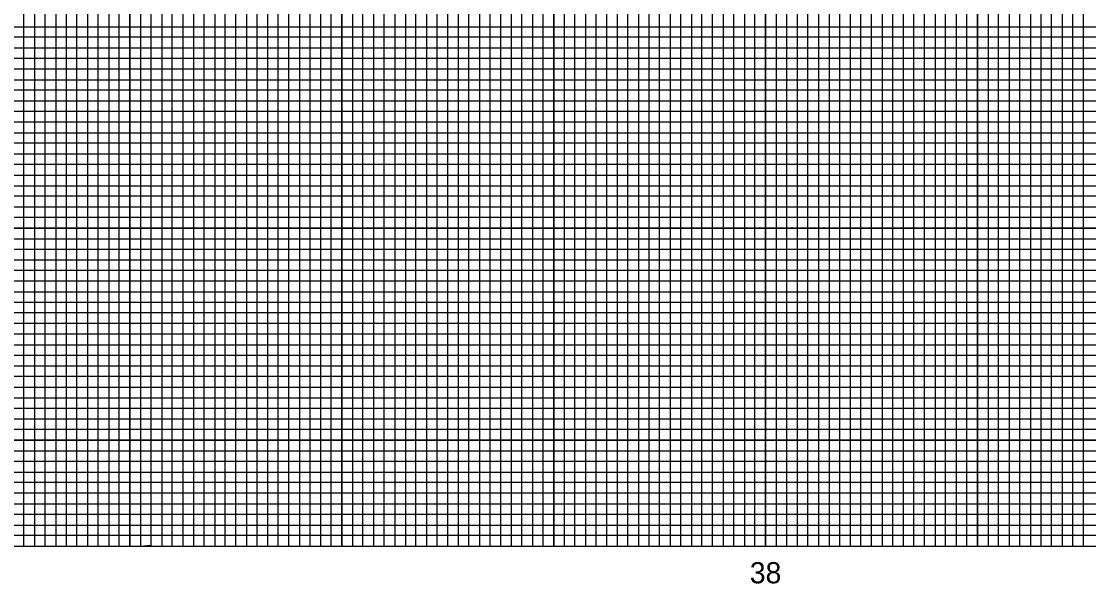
# Model space of a CAD drawing. Extents: x 1648862 to 1650739, y 844691 to 845791.
# Drawn here: x 1649828 to 1650332, y 845248 to 845514 of the extents above; entities that cross this region are included whole.
import ezdxf

# ---------------------------------------------------------------- set-up
doc = ezdxf.new("R2010")
doc.units = 0
for name, color, linetype in [('Prop Conc Barrier Precast Reinforced Single Face', 7, 'Continuous'), ('Prop Conc Expressway Gutter', 7, 'Continuous'), ('Prop DGN Element Guardrail', 7, 'Continuous'), ('Prop Dimension', 7, 'Continuous'), ('Prop Dimension Text', 7, 'Continuous'), ('Prop Easement Construction Station Offsets', 7, 'Continuous')]:
    doc.layers.add(name, color=color, linetype=linetype)

msp = doc.modelspace()

# ---------------------------------------------------------------- linework, layer by layer
at = {"layer": 'Prop Conc Expressway Gutter'}
for p, q in [((1649079.28, 845511.02), (1650479.28, 845511.02)), ((1650479.28, 845506.02), (1649079.28, 845506.02)), ((1649079.28, 845501.02), (1650479.28, 845501.02)), ((1650479.28, 845496.02), (1649079.28, 845496.02)), ((1649079.28, 845486.02), (1650479.28, 845486.02)), ((1650479.28, 845481.02), (1649079.28, 845481.02)), ((1649079.28, 845476.02), (1650479.28, 845476.02)), ((1650479.28, 845471.02), (1649079.28, 845471.02)), ((1649079.28, 845461.02), (1650479.28, 845461.02)), ((1650479.28, 845456.02), (1649079.28, 845456.02)), ((1649079.28, 845451.02), (1650479.28, 845451.02)), ((1650479.28, 845446.02), (1649079.28, 845446.02)), ((1649079.28, 845436.02), (1650479.28, 845436.02)), ((1650479.28, 845431.02), (1649079.28, 845431.02)), ((1649079.28, 845426.02), (1650479.28, 845426.02)), ((1650479.28, 845421.02), (1649079.28, 845421.02)), ((1649079.28, 845411.02), (1650479.28, 845411.02)), ((1650479.28, 845406.02), (1649079.28, 845406.02)), ((1649079.28, 845401.02), (1650479.28, 845401.02)), ((1650479.28, 845396.02), (1649079.28, 845396.02)), ((1649079.28, 845386.02), (1650479.28, 845386.02)), ((1650479.28, 845381.02), (1649079.28, 845381.02)), ((1650479.28, 845376.02), (1649079.28, 845376.02)), ((1650479.28, 845371.02), (1649079.28, 845371.02)), ((1649079.28, 845361.02), (1650479.28, 845361.02)), ((1650479.28, 845356.02), (1649079.28, 845356.02)), ((1649079.28, 845351.02), (1650479.28, 845351.02)), ((1650479.28, 845346.02), (1649079.28, 845346.02)), ((1649079.28, 845336.02), (1650479.28, 845336.02)), ((1650479.28, 845331.02), (1649079.28, 845331.02)), ((1649079.28, 845326.02), (1650479.28, 845326.02)), ((1650479.28, 845321.02), (1649079.28, 845321.02)), ((1649079.28, 845311.02), (1650479.28, 845311.02)), ((1650479.28, 845306.02), (1649079.28, 845306.02)), ((1649079.28, 845301.02), (1650479.28, 845301.02)), ((1650479.28, 845296.02), (1649079.28, 845296.02)), ((1649079.28, 845286.02), (1650479.28, 845286.02)), ((1650479.28, 845281.02), (1649079.28, 845281.02)), ((1649079.28, 845276.02), (1650479.28, 845276.02)), ((1650159.28, 845266.02), (1650164.28, 845266.02))]:
    msp.add_line(p, q, dxfattribs=at)
for points in [[(1649834.28, 845766.02), (1649834.28, 845266.02), (1649839.28, 845266.02), (1649839.28, 845766.02)], [(1649844.28, 845766.02), (1649844.28, 845266.02), (1649849.28, 845266.02), (1649849.28, 845766.02)], [(1649859.28, 845766.02), (1649859.28, 845266.02), (1649864.28, 845266.02), (1649864.28, 845766.02)], [(1649869.28, 845766.02), (1649869.28, 845266.02), (1649874.28, 845266.02), (1649874.28, 845766.02)], [(1649884.28, 845766.02), (1649884.28, 845266.02), (1649888.98, 845266.57), (1649889.28, 845266.02), (1649889.28, 845766.02)], [(1649894.28, 845766.02), (1649894.28, 845266.02), (1649899.28, 845266.02), (1649899.28, 845766.02)], [(1649909.28, 845766.02), (1649909.28, 845266.02), (1649914.28, 845266.02)], [(1649914.28, 845266.02), (1649914.28, 845766.02)], [(1649919.28, 845766.02), (1649919.28, 845266.02), (1649924.28, 845266.02), (1649924.28, 845766.02)], [(1649934.28, 845766.02), (1649934.28, 845266.02), (1649939.28, 845266.02), (1649939.28, 845766.02)], [(1649944.28, 845766.02), (1649944.28, 845266.02), (1649949.28, 845266.02), (1649949.28, 845766.02)], [(1649959.28, 845766.02), (1649959.28, 845266.02), (1649964.28, 845266.02), (1649964.28, 845766.02)], [(1649969.28, 845766.02), (1649969.28, 845266.02), (1649974.28, 845266.02), (1649974.28, 845766.02)], [(1649984.28, 845766.02), (1649984.28, 845266.02), (1649989.28, 845266.02), (1649989.28, 845766.02)], [(1649994.28, 845766.02), (1649994.28, 845266.02), (1649999.28, 845266.02), (1649999.28, 845766.02)], [(1650009.28, 845766.02), (1650009.28, 845266.02), (1650014.28, 845266.02), (1650014.28, 845766.02)], [(1650019.28, 845766.02), (1650019.28, 845266.02), (1650024.28, 845266.02), (1650024.28, 845766.02)], [(1650034.28, 845766.02), (1650034.28, 845266.02), (1650039.28, 845266.02), (1650039.28, 845766.02)], [(1650044.28, 845766.02), (1650044.28, 845266.02), (1650049.28, 845266.02), (1650049.28, 845766.02)], [(1650059.28, 845766.02), (1650059.28, 845266.02), (1650064.28, 845266.02), (1650064.28, 845766.02)], [(1650069.28, 845766.02), (1650069.28, 845266.02), (1650074.28, 845266.02), (1650074.28, 845766.02)], [(1650084.28, 845766.02), (1650084.28, 845266.02), (1650089.28, 845266.02), (1650089.28, 845766.02)], [(1650094.28, 845766.02), (1650094.28, 845266.02), (1650099.28, 845266.02), (1650099.28, 845766.02)], [(1650109.28, 845766.02), (1650109.28, 845266.02), (1650114.28, 845266.02), (1650114.28, 845766.02)], [(1650119.28, 845766.02), (1650119.28, 845266.02), (1650124.28, 845266.02), (1650124.28, 845766.02)], [(1650134.28, 845766.02), (1650134.28, 845266.02), (1650139.28, 845266.02), (1650139.28, 845766.02)], [(1650144.28, 845766.02), (1650144.28, 845266.02), (1650149.28, 845266.02), (1650149.28, 845766.02)], [(1650159.28, 845766.02), (1650159.28, 845266.02), (1650164.28, 845266.02), (1650164.28, 845766.02)], [(1650169.28, 845766.02), (1650169.28, 845266.02), (1650174.28, 845266.02), (1650174.28, 845766.02)], [(1650184.28, 845738.96), (1650184.28, 845266.02), (1650189.28, 845266.02), (1650189.28, 845738.96)], [(1650194.28, 845738.96), (1650194.28, 845266.02), (1650199.28, 845266.02), (1650199.28, 845738.96)], [(1650209.28, 845738.96), (1650209.28, 845266.02), (1650214.28, 845266.02), (1650214.28, 845738.96)], [(1650219.28, 845266.02), (1650224.28, 845266.02), (1650224.28, 845738.96)], [(1650219.28, 845738.96), (1650219.28, 845266.02)], [(1650234.28, 845738.96), (1650234.28, 845266.02), (1650239.28, 845266.02), (1650239.28, 845738.96)], [(1650244.28, 845738.96), (1650244.28, 845266.02), (1650249.28, 845266.02), (1650249.28, 845738.96)], [(1650259.28, 845738.96), (1650259.28, 845266.02), (1650264.28, 845266.02), (1650264.28, 845738.96)], [(1650269.28, 845738.96), (1650269.28, 845266.02), (1650274.28, 845266.02), (1650274.28, 845738.96)], [(1650284.28, 845738.96), (1650284.28, 845266.02), (1650289.28, 845266.02), (1650289.28, 845738.96)], [(1650294.28, 845738.96), (1650294.28, 845266.02), (1650299.28, 845266.02), (1650299.28, 845738.96)], [(1650309.28, 845738.96), (1650309.28, 845266.02), (1650314.28, 845266.02), (1650314.28, 845738.96)], [(1650319.28, 845738.96), (1650319.28, 845266.02), (1650324.28, 845266.02), (1650324.28, 845738.96)], [(1650479.28, 845271.02), (1649079.28, 845271.02)]]:
    msp.add_lwpolyline(points, dxfattribs=at)
at = {"layer": 'Prop DGN Element Guardrail'}
msp.add_line((1649029.28, 845266.02), (1650529.28, 845266.02), dxfattribs=at)
at = {"layer": 'Prop Dimension'}
for points in [[(1649779.28, 845266.02), (1649829.28, 845266.02), (1649829.28, 845766.02), (1649879.28, 845766.02), (1649879.28, 845266.02), (1649929.28, 845266.02), (1649929.28, 845766.02), (1649979.28, 845766.02), (1649979.28, 845266.02), (1650029.28, 845266.02), (1650029.28, 845766.02), (1650079.28, 845766.02), (1650079.28, 845266.02), (1650129.28, 845266.02), (1650129.28, 845766.02), (1650179.28, 845766.02), (1650179.28, 845266.02), (1650229.28, 845266.02), (1650229.28, 845738.96)], [(1650279.28, 845738.96), (1650279.28, 845266.02), (1650329.28, 845266.02), (1650329.28, 845766.02), (1650355.58, 845766.02)], [(1650529.28, 845466.02), (1649029.28, 845466.02), (1649029.28, 845416.02), (1650529.28, 845416.02)], [(1650529.28, 845366.02), (1649029.28, 845366.02), (1649029.28, 845366.02), (1649029.28, 845316.02), (1650529.28, 845316.02)]]:
    msp.add_lwpolyline(points, dxfattribs=at)
at = {"layer": 'Prop Dimension Text'}
for points in [[(1649804.28, 845266.02), (1649854.28, 845266.02), (1649854.28, 845766.02), (1649904.28, 845766.02), (1649904.28, 845266.02), (1649954.28, 845266.02), (1649954.28, 845766.02), (1650004.28, 845766.02), (1650004.28, 845266.02), (1650054.28, 845266.02), (1650054.28, 845766.02), (1650104.28, 845766.02), (1650104.28, 845266.02), (1650154.28, 845266.02), (1650154.28, 845766.02), (1650204.28, 845766.02)], [(1650204.28, 845738.96), (1650204.28, 845266.02), (1650254.28, 845266.02), (1650254.28, 845738.96)], [(1650304.28, 845738.96), (1650304.28, 845266.02), (1650354.28, 845266.02), (1650354.28, 845604.97)], [(1650529.28, 845491.02), (1649029.28, 845491.02), (1649029.28, 845441.02), (1650529.28, 845441.02)], [(1650529.28, 845391.02), (1649029.28, 845391.02), (1649029.28, 845341.02), (1650529.28, 845341.02)], [(1650529.28, 845291.02), (1649029.28, 845291.02)]]:
    msp.add_lwpolyline(points, dxfattribs=at)
at = {"layer": 'Prop Easement Construction Station Offsets'}
for p, q in [((1649829.28, 845266.02), (1649829.28, 845766.02)), ((1649879.28, 845266.02), (1649879.28, 845766.02)), ((1649929.28, 845266.02), (1649929.28, 845766.02)), ((1649979.28, 845266.02), (1649979.28, 845766.02)), ((1650029.28, 845266.02), (1650029.28, 845766.02)), ((1650079.28, 845266.02), (1650079.28, 845766.02)), ((1650129.28, 845266.02), (1650129.28, 845766.02)), ((1650179.28, 845266.02), (1650179.28, 845766.02)), ((1650229.28, 845266.02), (1650229.28, 845738.96)), ((1650279.28, 845266.02), (1650279.28, 845738.96)), ((1650329.28, 845266.02), (1650329.28, 845628.47)), ((1650529.28, 845466.02), (1649029.28, 845466.02)), ((1650529.28, 845416.02), (1649029.28, 845416.02)), ((1650529.28, 845366.02), (1649029.28, 845366.02)), ((1650529.28, 845316.02), (1649029.28, 845316.02))]:
    msp.add_line(p, q, dxfattribs=at)

# ---------------------------------------------------------------- texts
at = {"layer": 'Prop Conc Barrier Precast Reinforced Single Face'}
msp.add_text('38', height=10, dxfattribs=at).set_placement((1650171.86, 845248.52))

doc.saveas('drawing.dxf')
